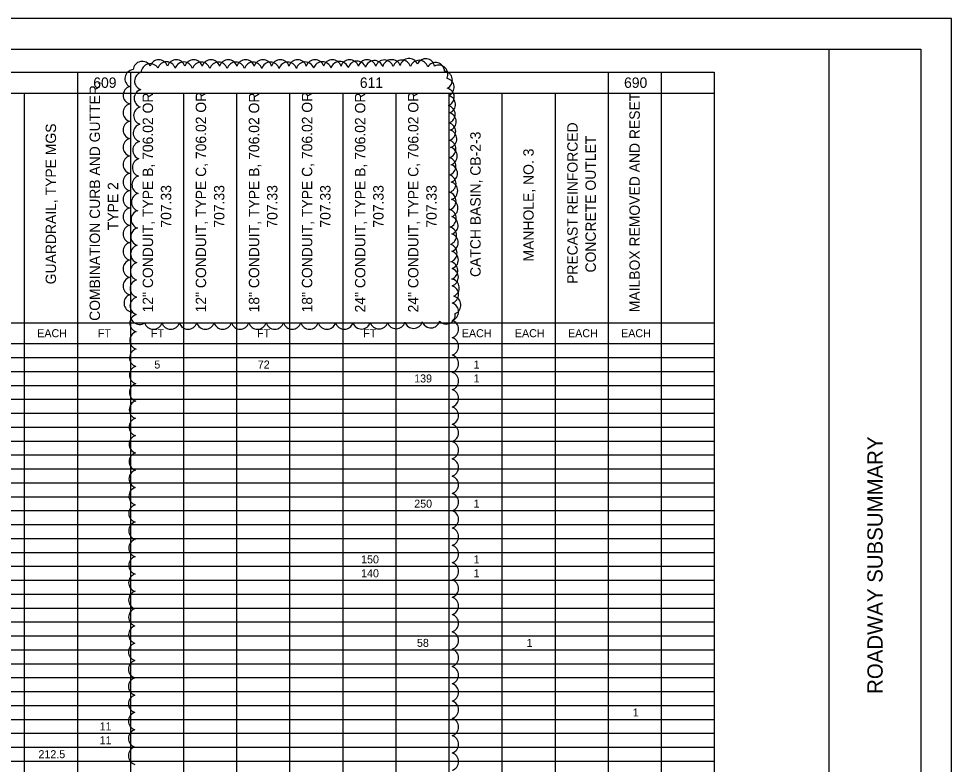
# Model space of a CAD drawing. Extents: x 0 to 37.4, y 0 to 22.
# Drawn here: x 18.72 to 34, y 9.78 to 22 of the extents above; entities that cross this region are included whole.
import ezdxf

# ---------------------------------------------------------------- set-up
doc = ezdxf.new("R2010")
doc.units = 0
for name, color, linetype in [('SC_Scratch1', 7, 'Continuous'), ('SH_Border', 7, 'Continuous'), ('SH_Cut_Line', 7, 'Continuous'), ('SH_Data', 7, 'Continuous'), ('SH_Text', 7, 'Continuous')]:
    doc.layers.add(name, color=color, linetype=linetype)

msp = doc.modelspace()

# ---------------------------------------------------------------- linework, layer by layer
at = {"layer": 'SC_Scratch1'}
for centre, start, end in [((20.748, 21.15), 28.9957, 173.9957), ((20.879, 21.112), 31.6272, 176.6272), ((21.02, 21.177), 17.5, 162.5), ((21.147, 21.143), 16.8439, 161.8439), ((21.305, 21.177), 17.5, 162.5), ((21.43, 21.141), 17.1226, 162.1226), ((21.589, 21.177), 17.5, 162.5), ((21.714, 21.139), 17.2733, 162.2733), ((21.873, 21.177), 17.5, 162.5), ((21.998, 21.138), 17.3714, 162.3714), ((22.157, 21.177), 17.5, 162.5), ((22.281, 21.138), 17.4419, 162.4419), ((22.441, 21.177), 17.5, 162.5), ((22.565, 21.138), 17.5034, 162.5034), ((22.726, 21.177), 17.5, 162.5), ((22.848, 21.138), 17.6294, 162.6294), ((23.01, 21.177), 17.5, 162.5), ((23.132, 21.139), 17.7949, 162.7949), ((23.294, 21.177), 17.497, 162.497), ((23.415, 21.141), 17.9967, 162.9967), ((23.578, 21.177), 17.4649, 162.4649), ((23.699, 21.144), 18.2504, 163.2504), ((23.862, 21.177), 17.4182, 162.4182), ((23.983, 21.149), 18.5826, 163.5826), ((24.146, 21.177), 17.3589, 162.3589), ((24.266, 21.155), 19.0452, 164.0452), ((24.431, 21.176), 17.28, 162.28), ((24.55, 21.165), 19.7549, 164.7549), ((24.715, 21.174), 17.1675, 162.1675), ((24.834, 21.179), 21.0657, 166.0657), ((24.999, 21.172), 16.9876, 161.9876), ((25.118, 21.199), 22.0945, 167.0945), ((25.283, 21.169), 16.6217, 161.6217), ((25.391, 21.194), 10.8133, 155.8133), ((25.552, 21.132), 3.0201, 148.0201), ((25.606, 21.091), 332.5611, 117.5611), ((20.614, 21.017), 95.6133, 240.6133), ((20.772, 20.978), 106.0409, 251.0409), ((25.679, 20.993), 296.5476, 81.5476), ((25.708, 20.876), 293.518, 78.518), ((20.586, 20.746), 107.4412, 252.4412), ((20.765, 20.694), 106.0409, 251.0409), ((25.71, 20.715), 291.3059, 76.3059), ((25.73, 20.596), 290.4767, 75.4767), ((20.586, 20.461), 107.5, 252.5), ((20.757, 20.411), 106.0409, 251.0409), ((25.725, 20.432), 289.591, 74.591), ((20.586, 20.177), 107.5, 252.5), ((25.742, 20.314), 289.5303, 74.5303), ((20.75, 20.128), 106.0409, 251.0409), ((25.733, 20.149), 288.6468, 73.6468), ((25.751, 20.031), 289.0131, 74.0131), ((20.586, 19.893), 107.5, 252.5), ((20.743, 19.844), 106.0409, 251.0409), ((25.737, 19.865), 288.0266, 73.0266), ((25.758, 19.748), 288.6745, 73.6745), ((20.586, 19.609), 107.5, 252.5), ((25.738, 19.582), 287.6038, 72.6038), ((20.736, 19.561), 106.0409, 251.0409), ((25.763, 19.465), 288.4306, 73.4306), ((20.586, 19.324), 107.5, 252.5), ((20.729, 19.278), 106.0409, 251.0409), ((25.739, 19.297), 287.6635, 72.6635), ((25.767, 19.181), 288.2441, 73.2441), ((20.586, 19.04), 107.5, 252.5), ((20.722, 18.994), 106.2021, 251.2021), ((25.74, 19.013), 287.912, 72.912), ((25.771, 18.898), 288.0955, 73.0955), ((20.586, 18.756), 107.5, 252.5), ((20.716, 18.711), 106.4417, 251.4417), ((25.743, 18.728), 288.2362, 73.2362), ((25.773, 18.615), 287.9734, 72.9734), ((20.586, 18.472), 107.5, 252.5), ((20.711, 18.428), 106.6056, 251.6056), ((25.748, 18.444), 288.6847, 73.6847), ((25.775, 18.331), 287.8709, 72.8709), ((20.586, 18.188), 107.5, 252.5), ((20.707, 18.144), 106.7269, 251.7269), ((25.756, 18.159), 289.3654, 74.3654), ((25.777, 18.048), 287.7831, 72.7831), ((20.586, 17.903), 107.5, 252.5), ((20.703, 17.861), 106.8212, 251.8212), ((25.768, 17.874), 290.5942, 75.5942), ((25.778, 17.765), 287.7069, 72.7069), ((20.586, 17.619), 107.5, 252.5), ((20.7, 17.578), 106.8974, 251.8974), ((25.792, 17.589), 294.0071, 79.0071), ((25.779, 17.481), 287.6399, 72.6399), ((20.599, 17.34), 112.7554, 257.7554), ((20.697, 17.294), 106.9606, 251.9606), ((25.819, 17.307), 291.9107, 76.9107), ((25.779, 17.198), 287.5804, 72.5804), ((20.695, 17.011), 107.0141, 252.0141), ((20.706, 17.14), 158.7419, 303.7419), ((25.727, 17.146), 223.8145, 8.8145), ((20.931, 17.061), 197.5, 342.5), ((21.215, 17.061), 197.5, 342.5), ((21.499, 17.061), 197.5, 342.5), ((21.783, 17.061), 197.5, 342.5), ((22.068, 17.061), 197.5, 342.5), ((22.352, 17.061), 197.5, 342.5), ((22.636, 17.061), 197.5, 342.5), ((22.92, 17.061), 197.5, 342.5), ((23.204, 17.061), 197.5, 342.5), ((23.488, 17.061), 197.535, 342.535), ((23.773, 17.062), 197.6219, 342.6219), ((24.057, 17.062), 197.729, 342.729), ((24.341, 17.064), 197.8654, 342.8654), ((24.625, 17.066), 198.0475, 343.0475), ((24.909, 17.069), 198.3086, 343.3086), ((25.193, 17.075), 198.7307, 343.7307), ((25.476, 17.083), 199.6121, 344.6121), ((25.78, 16.914), 287.5271, 72.5271), ((20.693, 16.728), 107.0601, 252.0601), ((25.78, 16.631), 287.5001, 72.5001), ((20.69, 16.444), 107.1003, 252.1003), ((25.78, 16.347), 287.5, 72.5), ((20.689, 16.161), 107.1358, 252.1358), ((25.78, 16.064), 287.5, 72.5), ((20.687, 15.877), 107.1674, 252.1674), ((25.78, 15.781), 287.5, 72.5), ((20.685, 15.594), 107.1959, 252.1959), ((25.78, 15.497), 287.5, 72.5), ((20.684, 15.31), 107.2216, 252.2216), ((25.78, 15.214), 287.5, 72.5), ((20.682, 15.027), 107.245, 252.245), ((25.78, 14.93), 287.5, 72.5), ((20.681, 14.744), 107.2665, 252.2665), ((25.78, 14.647), 287.5, 72.5), ((20.68, 14.46), 107.2862, 252.2862), ((25.78, 14.363), 287.5, 72.5), ((20.679, 14.177), 107.3045, 252.3045), ((25.78, 14.08), 287.5, 72.5), ((20.678, 13.893), 107.3214, 252.3214), ((25.78, 13.796), 287.5, 72.5), ((20.677, 13.61), 107.3371, 252.3371), ((25.78, 13.513), 287.5, 72.5), ((20.677, 13.326), 107.3519, 252.3519), ((25.78, 13.23), 287.5, 72.5), ((20.676, 13.043), 107.3657, 252.3657), ((25.78, 12.946), 287.5, 72.5), ((20.675, 12.759), 107.3786, 252.3786), ((25.78, 12.663), 287.5, 72.5), ((20.675, 12.476), 107.3909, 252.3909), ((25.78, 12.379), 287.5, 72.5), ((20.674, 12.193), 107.4024, 252.4024), ((25.78, 12.096), 287.5, 72.5), ((20.674, 11.909), 107.4133, 252.4133), ((25.78, 11.812), 287.5, 72.5), ((20.673, 11.626), 107.4236, 252.4236), ((25.78, 11.529), 287.5, 72.5), ((20.673, 11.342), 107.4335, 252.4335), ((25.78, 11.245), 287.5, 72.5), ((20.673, 11.059), 107.4428, 252.4428), ((25.78, 10.962), 287.5, 72.5), ((20.672, 10.775), 107.4517, 252.4517), ((25.78, 10.678), 287.5, 72.5), ((20.672, 10.492), 107.4602, 252.4602), ((25.78, 10.395), 287.5, 72.5), ((20.672, 10.208), 107.4683, 252.4683), ((25.78, 10.112), 287.5, 72.5), ((20.672, 9.925), 107.4761, 252.4761), ((25.78, 9.828), 287.5, 72.5)]:
    msp.add_arc(centre, 0.149, start, end, dxfattribs=at)
at = {"layer": 'SH_Border'}
msp.add_line((32, 0.5), (32, 21.5), dxfattribs=at)
msp.add_lwpolyline([(1.5, 21.5), (33.5, 21.5), (33.5, 0.5), (1.5, 0.5)], close=True, dxfattribs=at)
at = {"layer": 'SH_Cut_Line'}
msp.add_lwpolyline([(0, 0), (34, 0), (34, 22), (0, 22)], close=True, dxfattribs=at)
at = {"layer": 'SH_Text'}
for p, q in [((3.398, 21.122), (30.117, 21.122)), ((19.686, 21.122), (19.686, 1.044)), ((20.555, 21.122), (20.555, 1.044)), ((28.379, 21.122), (28.379, 1.044)), ((29.248, 21.122), (29.248, 1.044)), ((30.117, 21.122), (30.117, 1.044)), ((9.255, 20.78), (30.117, 20.78)), ((18.817, 20.78), (18.817, 1.044)), ((21.425, 20.78), (21.425, 1.044)), ((22.294, 20.78), (22.294, 1.044)), ((23.163, 20.78), (23.163, 1.044)), ((24.032, 20.78), (24.032, 1.044)), ((24.902, 20.78), (24.902, 1.044)), ((25.771, 20.78), (25.771, 1.044)), ((26.64, 20.78), (26.64, 1.044)), ((27.509, 20.78), (27.509, 1.044)), ((9.255, 17.018), (30.117, 17.018)), ((3.398, 16.676), (30.117, 16.676)), ((3.398, 16.448), (30.117, 16.448)), ((3.398, 16.22), (30.117, 16.22)), ((3.398, 15.992), (30.117, 15.992)), ((3.398, 15.764), (30.117, 15.764)), ((3.398, 15.536), (30.117, 15.536)), ((3.398, 15.308), (30.117, 15.308)), ((3.398, 15.08), (30.117, 15.08)), ((3.398, 14.852), (30.117, 14.852)), ((3.398, 14.624), (30.117, 14.624)), ((3.398, 14.396), (30.117, 14.396)), ((3.398, 14.168), (30.117, 14.168)), ((3.398, 13.94), (30.117, 13.94)), ((3.398, 13.712), (30.117, 13.712)), ((3.398, 13.484), (30.117, 13.484)), ((3.398, 13.256), (30.117, 13.256)), ((3.398, 13.028), (30.117, 13.028)), ((3.398, 12.8), (30.117, 12.8)), ((3.398, 12.572), (30.117, 12.572)), ((3.398, 12.344), (30.117, 12.344)), ((3.398, 12.116), (30.117, 12.116)), ((3.398, 11.888), (30.117, 11.888)), ((3.398, 11.66), (30.117, 11.66)), ((3.398, 11.432), (30.117, 11.432)), ((3.398, 11.204), (30.117, 11.204)), ((3.398, 10.976), (30.117, 10.976)), ((3.398, 10.748), (30.117, 10.748)), ((3.398, 10.52), (30.117, 10.52)), ((3.398, 10.292), (30.117, 10.292)), ((3.398, 10.064), (30.117, 10.064)), ((3.398, 9.836), (30.117, 9.836))]:
    msp.add_line(p, q, dxfattribs=at)

# ---------------------------------------------------------------- texts
at = {"layer": 'SH_Data'}
msp.add_text('ROADWAY SUBSUMMARY', height=0.25, rotation=90, dxfattribs=at).set_placement((32.875, 10.938))
at = {"layer": 'SH_Text'}
for s, height, p in [('COMBINATION CURB AND GUTTER, ', 0.17043, (20.057, 17.049)), ('12" CONDUIT, TYPE B, 706.02 OR ', 0.17043, (20.926, 17.187)), ('12" CONDUIT, TYPE C, 706.02 OR ', 0.17043, (21.795, 17.187)), ('18" CONDUIT, TYPE B, 706.02 OR ', 0.17043, (22.665, 17.187)), ('18" CONDUIT, TYPE C, 706.02 OR ', 0.17043, (23.534, 17.187)), ('24" CONDUIT, TYPE B, 706.02 OR ', 0.17043, (24.403, 17.187)), ('24" CONDUIT, TYPE C, 706.02 OR ', 0.17043, (25.272, 17.187)), ('MAILBOX REMOVED AND RESET', 0.17043, (28.898, 17.19)), ('GUARDRAIL, TYPE MGS', 0.17043, (19.337, 17.648)), ('PRECAST REINFORCED ', 0.17043, (27.88, 17.654)), ('CATCH BASIN, CB-2-3', 0.17043, (26.291, 17.768)), ('CONCRETE OUTLET', 0.17043, (28.178, 17.841)), ('MANHOLE, NO. 3', 0.17043, (27.16, 18.022)), ('TYPE 2', 0.1704, (20.355, 18.535)), ('707.33', 0.1704, (21.224, 18.576)), ('707.33', 0.1704, (22.094, 18.576)), ('707.33', 0.1704, (22.963, 18.576)), ('707.33', 0.1704, (23.832, 18.576)), ('707.33', 0.1704, (24.701, 18.576)), ('707.33', 0.1704, (25.571, 18.576))]:
    msp.add_text(s, height=height, rotation=90, dxfattribs=at).set_placement(p)
for s, height, p in [('609', 0.1704, (19.947, 20.866)), ('611', 0.1704, (24.312, 20.866)), ('690', 0.1704, (28.64, 20.866)), ('EACH', 0.1311, (19.029, 16.781)), ('FT', 0.1311, (20.022, 16.781)), ('FT', 0.1311, (20.891, 16.781)), ('FT', 0.1311, (22.629, 16.781)), ('FT', 0.1311, (24.368, 16.781)), ('EACH', 0.1311, (25.983, 16.781)), ('EACH', 0.1311, (26.852, 16.781)), ('EACH', 0.1311, (27.722, 16.781)), ('EACH', 0.1311, (28.591, 16.781)), ('5', 0.131, (20.947, 16.268)), ('72', 0.1311, (22.641, 16.268)), ('1', 0.131, (26.175, 16.268)), ('139', 0.1311, (25.202, 16.04)), ('1', 0.131, (26.175, 16.04)), ('250', 0.1311, (25.203, 13.988)), ('1', 0.131, (26.175, 13.988)), ('150', 0.1311, (24.333, 13.076)), ('1', 0.131, (26.175, 13.076)), ('140', 0.1311, (24.333, 12.848)), ('1', 0.131, (26.175, 12.848)), ('58', 0.1311, (25.248, 11.708)), ('1', 0.131, (27.044, 11.708)), ('1', 0.131, (28.783, 10.568)), ('11', 0.1311, (20.05, 10.34)), ('11', 0.1311, (20.05, 10.112)), ('212.5', 0.1311, (19.049, 9.884))]:
    msp.add_text(s, height=height, dxfattribs=at).set_placement(p)

doc.saveas('drawing.dxf')
